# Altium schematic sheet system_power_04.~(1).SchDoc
size 431 x 279 mm; Date: Not shown in title block; ApprovedBy: Not shown in title block; CheckedBy: Not shown in title block; Author: Not shown in title block; CompanyName: Not shown in title block; Engineer: Not shown in title block; Organization: Not shown in title block; Address1: Not shown in title block; Address2: Not shown in title block; Address3: Not shown in title block; Address4: Not shown in title block; DocumentNumber: 37; Revision: Use project parameter SCH_Rev; SheetNumber: 37; SheetTotal: 38; PageSetup: Record=PageOptions¦CenterHorizontal=True¦CenterVertical=True¦PrintScale=1.00¦XCorrection=1.00¦YCorrection=1.00¦PrintKind=0¦BorderSize=5000000¦LeftOffset=0¦BottomOffset=0¦Orientation=2¦PaperLength=1000¦PaperWidth=1000¦Scale=100¦PaperSource=15¦PrintQuality=600¦MediaType=1¦DitherType=10¦PaperKind=Letter¦PrintScaleMode=1
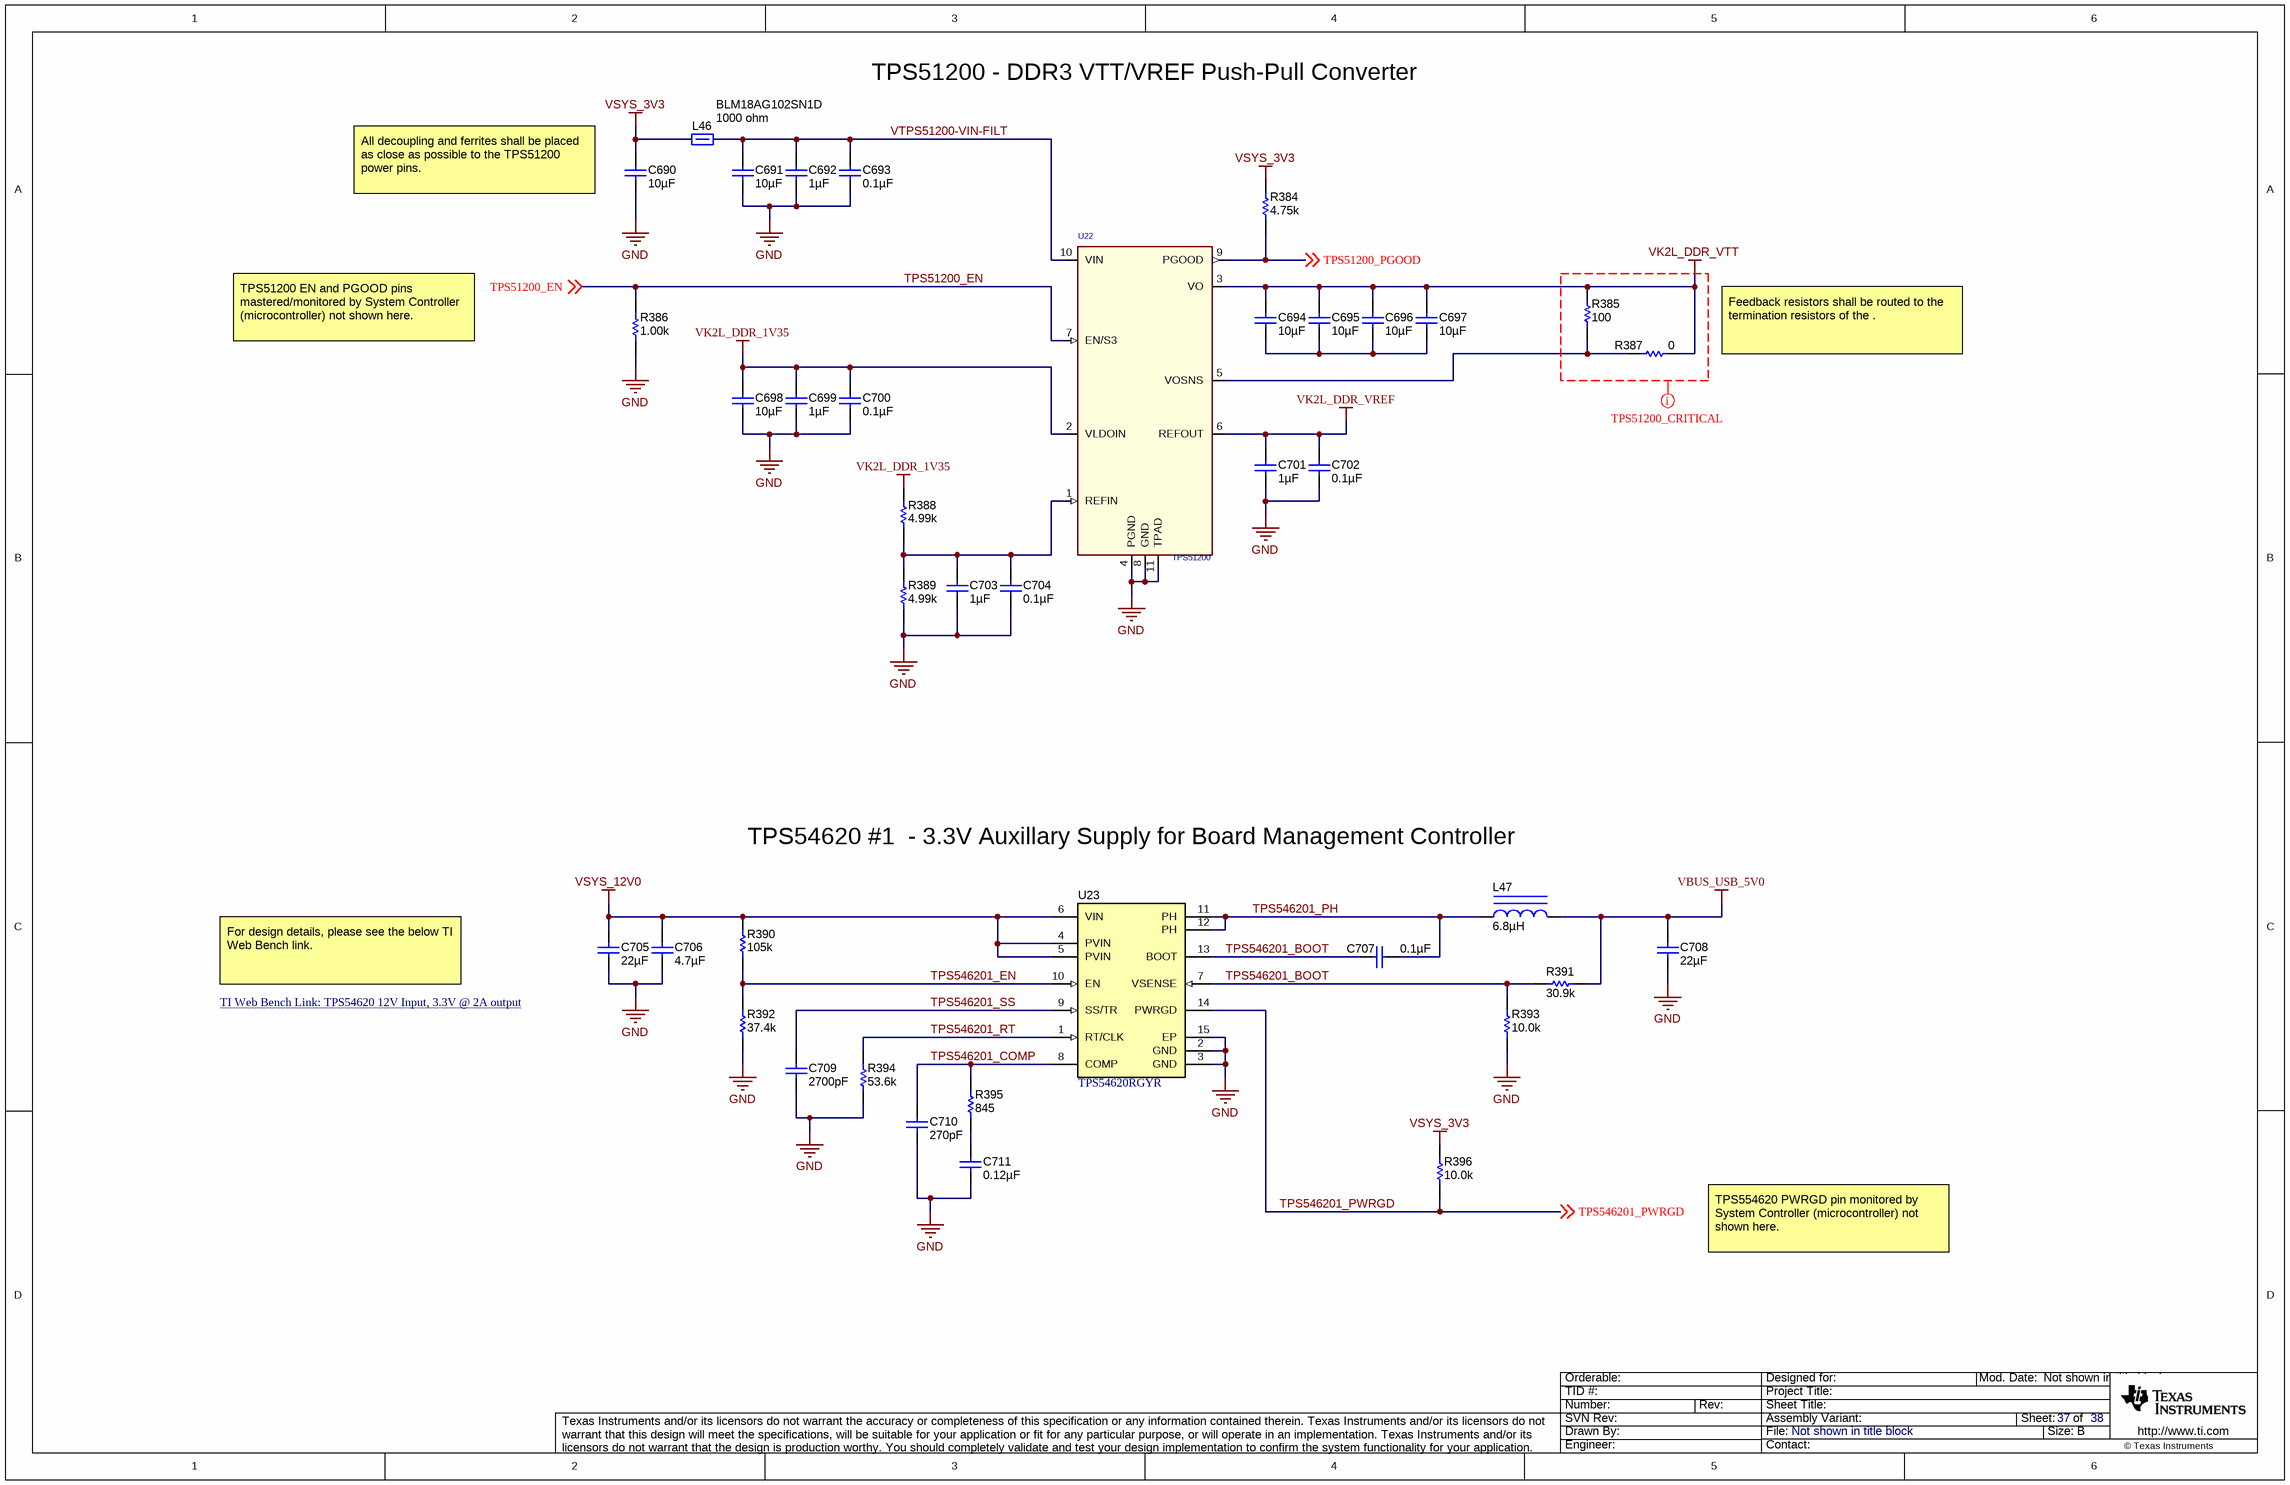
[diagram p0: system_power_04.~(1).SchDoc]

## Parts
C690  ValueDisplayed: 10µF  [0805_HV]  (hidden comment: GRM21BF50J106ZE01L)
C691  ValueDisplayed: 10µF  [0805_HV]  (hidden comment: GRM21BF50J106ZE01L)
C692  ValueDisplayed: 1µF  [0603]  (hidden comment: GRM188R70J105KA01D)
C693  ValueDisplayed: 0.1µF  [0603]  (hidden comment: GRM188R70J104KA01D)
C694  ValueDisplayed: 10µF  [0805_HV]  (hidden comment: GRM21BF50J106ZE01L)
C695  ValueDisplayed: 10µF  [0805_HV]  (hidden comment: GRM21BF50J106ZE01L)
C696  ValueDisplayed: 10µF  [0805_HV]  (hidden comment: GRM21BF50J106ZE01L)
C697  ValueDisplayed: 10µF  [0805_HV]  (hidden comment: GRM21BF50J106ZE01L)
C698  ValueDisplayed: 10µF  [0805_HV]  (hidden comment: GRM21BF50J106ZE01L)
C699  ValueDisplayed: 1µF  [0603]  (hidden comment: GRM188R70J105KA01D)
C700  ValueDisplayed: 0.1µF  [0603]  (hidden comment: GRM188R70J104KA01D)
C701  ValueDisplayed: 1µF  [0603]  (hidden comment: GRM188R70J105KA01D)
C702  ValueDisplayed: 0.1µF  [0603]  (hidden comment: GRM188R70J104KA01D)
C703  ValueDisplayed: 1µF  [0603]  (hidden comment: GRM188R70J105KA01D)
C704  ValueDisplayed: 0.1µF  [0603]  (hidden comment: GRM188R70J104KA01D)
C705  ValueDisplayed: 22µF  [1210_270]  (hidden comment: GRM32ER61E226KE15L)
C706  ValueDisplayed: 4.7µF  [0805_HV]  (hidden comment: GRM21BR61E475KA12L)
C707  ValueDisplayed: 0.1µF  [0805_HV]  (hidden comment: 08053C104KAT2A)
C708  ValueDisplayed: 22µF  [1210_270]  (hidden comment: GRM32ER61E226KE15L)
C709  ValueDisplayed: 2700pF  [0805_HV]  (hidden comment: CC0805KRX7R9BB272)
C710  ValueDisplayed: 270pF  [0402]  (hidden comment: GRM1555C1H271FA01D)
C711  ValueDisplayed: 0.12µF  [0402]  (hidden comment: GRM155C80J124KE01D)
L46  BLM18AG102SN1D  value 1000 ohm  [0603]
L47  ValueDisplayed: 6.8µH  [SRN6045]  (hidden comment: SRN6045-6R8Y)
R384  ValueDisplayed: 4.75k  [0402]  (hidden comment: CRCW04024K75FKED)
R385  ValueDisplayed: 100  [0402]  (hidden comment: CRCW0402100RFKED)
R386  ValueDisplayed: 1.00k  [0402]  (hidden comment: CRCW04021K00FKED)
R387  ValueDisplayed: 0  [0402]  (hidden comment: CRCW04020000Z0ED)
R388  ValueDisplayed: 4.99k  [0402]  (hidden comment: CRCW04024K99FKED)
R389  ValueDisplayed: 4.99k  [0402]  (hidden comment: CRCW04024K99FKED)
R390  ValueDisplayed: 105k  [0402]  (hidden comment: CRCW0402105KFKED)
R391  ValueDisplayed: 30.9k  [0402]  (hidden comment: CRCW040230K9FKED)
R392  ValueDisplayed: 37.4k  [0402]  (hidden comment: CRCW040237K4FKED)
R393  ValueDisplayed: 10.0k  [0402]  (hidden comment: CRCW040210K0DHEDP)
R394  ValueDisplayed: 53.6k  [0402]  (hidden comment: CRCW040253K6FKED)
R395  ValueDisplayed: 845  [0402]  (hidden comment: CRCW0402845RFKED)
R396  ValueDisplayed: 10.0k  [0402]  (hidden comment: CRCW040210K0DHEDP)
U22  TPS51200  [MSOP-10]
U23  TPS54620RGYR  [RHL0014A]

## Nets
GND: C690.2 C691.2 C692.2 C693.2 C698.2 C699.2 C700.2 C701.2 C702.2 C703.2 C704.2 C705.2 C706.2 C708.2 C709.2 C710.2 C711.2 R386.1 R389.1 R392.1 R393.1 R394.1 U22.4(PGND) U22.8(GND) U22.11(TPAD) U23.2(GND) U23.3(GND) U23.15(EP)
VBUS_USB_5V0: C708.1 L47.2 R391.2
VK2L_DDR_1V35: C698.1 C699.1 C700.1 R388.2 U22.2(VLDOIN)
VK2L_DDR_VREF: C701.1 C702.1 U22.6(REFOUT)
VK2L_DDR_VTT: C694.1 C695.1 C696.1 C697.1 R385.1 R387.1 U22.3(VO)
VSYS_3V3: C690.1 L46.1 R384.2 R396.2
VSYS_12V0: C705.1 C706.1 R390.2 U23.4(PVIN) U23.5(PVIN) U23.6(VIN)
TPS51200_EN: R386.2 U22.7(EN/S3) ; off-sheet TPS51200_EN
TPS51200_PGOOD: R384.1 U22.9(PGOOD) ; off-sheet TPS51200_PGOOD
TPS546201_BOOT: C707.2 R391.1 R393.2 U23.7(VSENSE) U23.13(BOOT)
TPS546201_COMP: C710.1 R395.2 U23.8(COMP)
TPS546201_EN: R390.1 R392.2 U23.10(EN)
TPS546201_PH: C707.1 L47.1 U23.11(PH) U23.12(PH)
TPS546201_PWRGD: R396.1 U23.14(PWRGD) ; off-sheet TPS546201_PWRGD
TPS546201_RT: R394.2 U23.1(RT/CLK)
TPS546201_SS: C709.1 U23.9(SS/TR)
VTPS51200-VIN-FILT: C691.1 C692.1 C693.1 L46.2 U22.10(VIN)
NetC694_2: C694.2 C695.2 C696.2 C697.2
NetC703_1: C703.1 C704.1 R388.1 R389.2 U22.1(REFIN)
NetC711_1: C711.1 R395.1
NetR385_2: R385.2 R387.2 U22.5(VOSNS)

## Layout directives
net class Undefined: VK2L_DDR_VTT

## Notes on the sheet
- TPS51200 - DDR3 VTT/VREF Push-Pull Converter
- (near C690) All decoupling and ferrites shall be placed as close as possible to the TPS51200 power pins.
- TPS51200 EN and PGOOD pins mastered/monitored by System Controller (microcontroller) not shown here.
- Feedback resistors shall be routed to the termination resistors of the .
- TPS54620 #1  - 3.3V Auxillary Supply for Board Management Controller
- For design details, please see the below TI Web Bench link.
- TI Web Bench Link: TPS54620 12V Input, 3.3V @ 2A output <https://webench.ti.com/appinfo/webench/scripts/SDP.cgi?ID=4D9808AAF39DD68E>
- TPS554620 PWRGD pin monitored by System Controller (microcontroller) not shown here.

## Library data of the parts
C690 C691 C694-C698 = GRM21BF50J106ZE01L: CAP, CERM, 10 µF, 6.3 V, +80/-20%, Y5V, 0805; Manufacturer: MuRata; Polarized: N; CompType: Capacitor; Value: 10uF; U/M: EA; Cap_F: 0.00001; Tolerance_%: 80; ESR_ohm: 0.1; Value1: 0.1 ohm; VDC_V: 6.3; Value2: 6.3V; TaMin_C: -30; TaMax_C: 85; Cap_Case: 0805; SizeArea_mm2: 2.5; SizeAreaWB_mm2: 6.75; SizeX_mm: 2; SizeY_mm: 1.25; SizeZ_mm: 1.45; AEC Category: Q200
C692 C699 C701 C703 = GRM188R70J105KA01D: CAP, CERM, 1 µF, 6.3 V, +/- 10%, X7R, 0603; Manufacturer: MuRata; Polarized: N; CompType: Capacitor; Value: 1uF; U/M: EA; Cap_F: 0.000001; Tolerance_%: 10; Value1: Unknown; VDC_V: 6.3; Value2: 6.3V; TaMin_C: -55; TaMax_C: 125; SizeArea_mm2: 1.28; SizeAreaWB_mm2: 4.68; SizeX_mm: 1.6; SizeY_mm: 0.8; SizeZ_mm: 1; AEC Category: Q200
C693 C700 C702 C704 = GRM188R70J104KA01D: CAP, CERM, 0.1 µF, 6.3 V, +/- 10%, X7R, 0603; Manufacturer: MuRata; Polarized: N; CompType: Capacitor; Value: 0.1uF; U/M: EA; Cap_F: 0.0000001; Tolerance_%: 10; Value1: Unknown; VDC_V: 6.3; Value2: 6.3V; TaMin_C: -55; TaMax_C: 125; SizeArea_mm2: 1.28; SizeAreaWB_mm2: 4.68; SizeX_mm: 1.6; SizeY_mm: 0.8; SizeZ_mm: 1; AEC Category: Q200
C705 C708 = GRM32ER61E226KE15L: CAP, CERM, 22 µF, 25 V, +/- 10%, X5R, 1210; Manufacturer: MuRata; Polarized: N; CompType: Capacitor; Value: 22uF; U/M: EA; Cap_F: 0.000022; Tolerance_%: 10; ESR_ohm: 0.002; Value1: 0.002 ohm; VDC_V: 25; Value2: 25V; IRMS_A: 3.67; TaMin_C: -55; TaMax_C: 85; Cap_Case: 1210; SizeArea_mm2: 8; SizeAreaWB_mm2: 14.7; SizeX_mm: 3.2; SizeY_mm: 2.5; SizeZ_mm: 2.7; AEC Category: Q200
C706 = GRM21BR61E475KA12L: CAP, CERM, 4.7 µF, 25 V, +/- 10%, X5R, 0805; Manufacturer: MuRata; Polarized: N; CompType: Capacitor; Value: 4.7uF; U/M: EA; Cap_F: 0.0000047; Tolerance_%: 10; ESR_ohm: 0.004; Value1: 0.004 ohm; VDC_V: 25; Value2: 25V; TaMin_C: -55; TaMax_C: 85; Cap_Case: 0805; SizeArea_mm2: 2.5; SizeAreaWB_mm2: 6.75; SizeX_mm: 2; SizeY_mm: 1.25; SizeZ_mm: 1.45; AEC Category: Q200
C707 = 08053C104KAT2A: CAP, CERM, 0.1 µF, 25 V, +/- 10%, X7R, 0805; Manufacturer: AVX; Polarized: N; CompType: Capacitor; Value: 0.1uF; U/M: EA; Cap_F: 0.0000001; Tolerance_%: 10; ESR_ohm: 0.28; Value1: 0.28 ohm; VDC_V: 25; Value2: 25V; TaMin_C: -55; TaMax_C: 125; Cap_Case: 0805; SizeArea_mm2: 2.5; SizeAreaWB_mm2: 6.75; SizeX_mm: 2; SizeY_mm: 1.25; SizeZ_mm: 1.45; AEC Category: Q200
C709 = CC0805KRX7R9BB272: CAP, CERM, 2700 pF, 50 V, +/- 10%, X7R, 0805; Manufacturer: Yageo America; Polarized: N; CompType: Capacitor; Value: 2700pF; U/M: EA; Cap_F: 0.0000000027; Tolerance_%: 10; Value1: Unknown; VDC_V: 50; Value2: 50V; TaMin_C: -55; TaMax_C: 125; Cap_Case: 0805; SizeArea_mm2: 2.5; SizeAreaWB_mm2: 6.75; SizeX_mm: 2; SizeY_mm: 1.25; SizeZ_mm: 1.45; AEC Category: Q200
C710 = GRM1555C1H271FA01D: CAP, CERM, 270 pF, 50 V, +/- 1%, C0G/NP0, 0402; Manufacturer: MuRata; Polarized: N; CompType: Capacitor; Value: 270pF; U/M: EA; Cap_F: 0.00000000027; Tolerance_%: 1; Value1: Unknown; VDC_V: 50; Value2: 50V; TaMin_C: -55; TaMax_C: 125; SizeArea_mm2: 0.5; SizeAreaWB_mm2: 3; SizeZ_mm: 0.6; AEC Category: Q200
C711 = GRM155C80J124KE01D: CAP, CERM, 0.12 µF, 6.3 V, +/- 10%, X6S, 0402; Manufacturer: MuRata; Polarized: N; CompType: Capacitor; Value: 0.12uF; U/M: EA; Cap_F: 0.00000012; Tolerance_%: 10; Value1: Unknown; VDC_V: 6.3; Value2: 6.3V; TaMin_C: -55; TaMax_C: 105; SizeArea_mm2: 0.5; SizeAreaWB_mm2: 3; SizeX_mm: 1; SizeZ_mm: 0.6; AEC Category: Q200
L46 = BLM18AG102SN1D: Ferrite Bead, 1000 ohm @ 100 MHz, 0.4 A, 0603; Manufacturer: MuRata; Imax_A: 0.4; DCR_ohm: 0.5; Value1: 0.5 ohm; Value2: 0.4A; ZTyp@100MHz_Ohm: 1000
L47 = SRN6045-6R8Y: Inductor, Drum Core, Ferrite, 6.8 µH, 2.8 A, 0.0473 ohm, SMD; Manufacturer: Bourns; Value: 6.8uH; Ind_H: 6.8E-6; Imax_A: 2.8; Irms: 2.8A @ 40C rise; Isat: 3.8A @ 30% inductance drop; DCR_ohm: 0.0473; Value2: 2.8A; AEC Category: Q200
R384 = CRCW04024K75FKED: RES, 4.75 k, 1%, 0.063 W, 0402; Manufacturer: Vishay-Dale; CompType: Resistor; Value: 4.75k; Res_ohm: 4750; Value_Code: 4k75; Tolerance_%: 1; Power_W: 0.063; Value2: 0.063W; VDC_V: 50; TempCo: 100 ppm/C; EIA_Code: E96; U/M: EA
R385 = CRCW0402100RFKED: RES, 100, 1%, 0.063 W, 0402; Manufacturer: Vishay-Dale; CompType: Resistor; Value: 100; Value_Code: 100R; Tolerance_%: 1; Power_W: 0.063; Value2: 0.063W; VDC_V: 50; TempCo: 100 ppm/C; SizeArea_mm2: 0.5; SizeZ_mm: 0.6; EIA_Code: E96; U/M: EA; AEC Category: Q200
R386 = CRCW04021K00FKED: RES, 1.00 k, 1%, 0.063 W, 0402; Manufacturer: Vishay-Dale; CompType: Resistor; Value: 1.00k; Res_ohm: 1000; Value_Code: 1k00; Tolerance_%: 1; Power_W: 0.063; Value2: 0.063W; VDC_V: 50; TempCo: 100 ppm/C; EIA_Code: E96; U/M: EA
R387 = CRCW04020000Z0ED: RES, 0, 5%, 0.063 W, 0402; Manufacturer: Vishay-Dale; CompType: Resistor; Value: 0; Value_Code: 0000; Tolerance_%: 5; Power_W: 0.063; Value2: 0.063W; VDC_V: 50; TempCo: 200 ppm/C; SizeArea_mm2: 0.5; SizeX_mm: 1; SizeZ_mm: 0.6; EIA_Code: E24; U/M: EA; AEC Category: Q200
R388 R389 = CRCW04024K99FKED: RES, 4.99 k, 1%, 0.063 W, 0402; Manufacturer: Vishay-Dale; CompType: Resistor; Value: 4.99k; Res_ohm: 4990; Value_Code: 4k99; Tolerance_%: 1; Power_W: 0.063; Value2: 0.063W; VDC_V: 50; TempCo: 100 ppm/C; SizeArea_mm2: 0.5; SizeZ_mm: 0.6; EIA_Code: E96; U/M: EA; AEC Category: Q200
R390 = CRCW0402105KFKED: RES, 105 k, 1%, 0.063 W, 0402; Manufacturer: Vishay-Dale; CompType: Resistor; Value: 105k; Res_ohm: 105000; Tolerance_%: 1; Power_W: 0.063; Value2: 0.063W; VDC_V: 50; TempCo: 100 ppm/C; SizeArea_mm2: 0.5; SizeZ_mm: 0.6; EIA_Code: E96; U/M: EA; AEC Category: Q200
R391 = CRCW040230K9FKED: RES, 30.9 k, 1%, 0.063 W, 0402; Manufacturer: Vishay-Dale; CompType: Resistor; Value: 30.9k; Res_ohm: 30900; Value_Code: 30k9; Tolerance_%: 1; Power_W: 0.063; Value2: 0.063W; VDC_V: 50; TempCo: 100 ppm/C; SizeArea_mm2: 0.5; SizeZ_mm: 0.6; EIA_Code: E96; U/M: EA; AEC Category: Q200
R392 = CRCW040237K4FKED: RES, 37.4 k, 1%, 0.063 W, 0402; Manufacturer: Vishay-Dale; CompType: Resistor; Value: 37.4k; Res_ohm: 37400; Value_Code: 37k4; Tolerance_%: 1; Power_W: 0.063; Value2: 0.063W; VDC_V: 50; TempCo: 100 ppm/C; SizeArea_mm2: 0.5; SizeZ_mm: 0.6; EIA_Code: E96; U/M: EA; AEC Category: Q200
R393 R396 = CRCW040210K0DHEDP: RES, 10.0 k, 0.5%, 0.063 W, 0402; Manufacturer: Vishay-Dale; CompType: Resistor; Value: 10.0k; Res_ohm: 10000; Value_Code: 10k0; Tolerance_%: 0.5; Power_W: 0.063; Value2: 0.063W; VDC_V: 50; TempCo: 50 ppm/C; SizeX_mm: 1; SizeZ_mm: 0.6; EIA_Code: E192; U/M: EA; AEC Category: Q200
R394 = CRCW040253K6FKED: RES, 53.6 k, 1%, 0.063 W, 0402; Manufacturer: Vishay-Dale; CompType: Resistor; Value: 53.6k; Res_ohm: 53600; Value_Code: 53k6; Tolerance_%: 1; Power_W: 0.063; Value2: 0.063W; VDC_V: 50; TempCo: 100 ppm/C; SizeArea_mm2: 0.5; SizeZ_mm: 0.6; EIA_Code: E96; U/M: EA; AEC Category: Q200
R395 = CRCW0402845RFKED: RES, 845, 1%, 0.063 W, 0402; Manufacturer: Vishay-Dale; CompType: Resistor; Value: 845; Value_Code: 845R; Tolerance_%: 1; Power_W: 0.063; Value2: 0.063W; VDC_V: 50; TempCo: 100 ppm/C; SizeArea_mm2: 0.5; SizeZ_mm: 0.6; EIA_Code: E96; U/M: EA; AEC Category: Q200
U22 = TPS51200: IC REG SINK/SOURCE DDR 10-SON; Vendor Part Number: 296-23830-1-ND; Part Number: TPS51200DRCT; Manufacturer: TI; Check: CHKNOV19A; In Stock: NA; Cost @ 1K: 1.4; Cost @ 100: 2.205; Cost @ 10: 3.15; Vendor: Digikey
U23 = TPS54620RGYR: Buck Step Down Regulator with 4.5 to 17 V Input and 0.8 to 15 V Output, -40 to 150 degC, 14-Pin VQFN (RGY), Green (RoHS & no Sb/Br); Manufacturer: Texas Instruments; Alternate PartNumber: Equivalent; Duty Cycle(Max)(%): 98; Iout(Max)(A): 6; Iq(Typ)(mA): 0.6; Rating: Catalog; Regulated Outputs(#): 1; SubFamily: Step-Down Regulator; Switch Current Limit(Typ)(A): 8; Synchronous Rectification: TRUE; Vin(Max)(V): 17; Vin(Min)(V): 4.5; Vout(Max)(V): 15; Vout(Min)(V): 0.8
